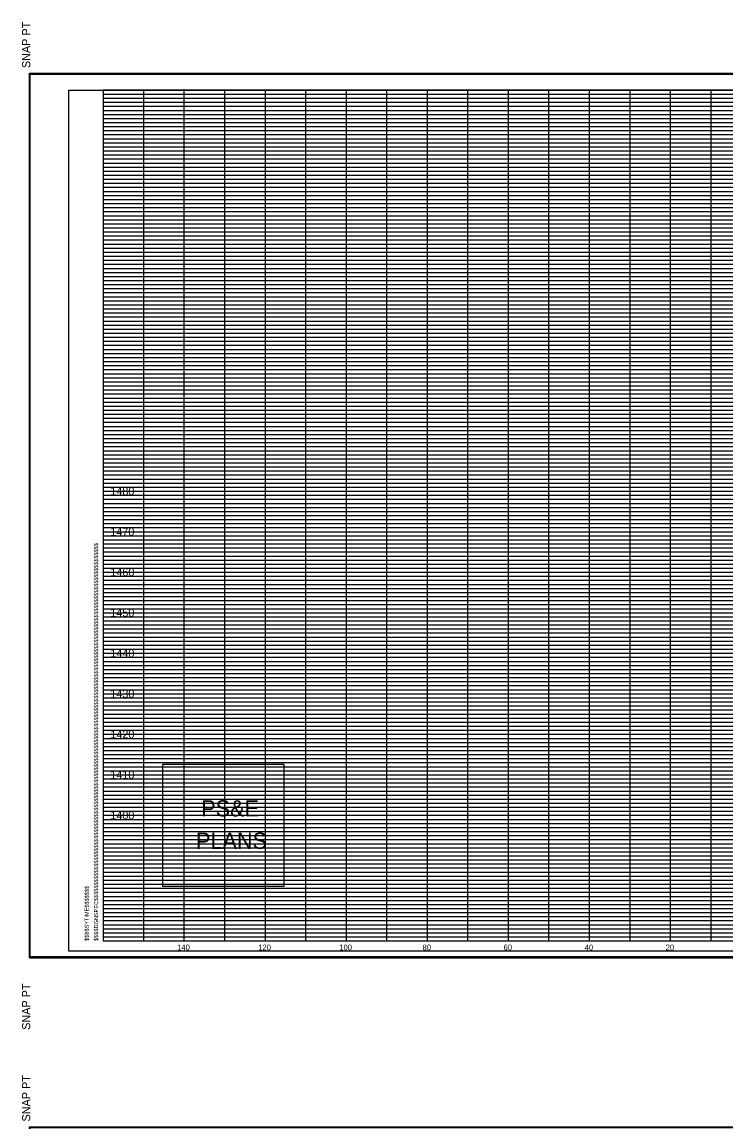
# Model space of a CAD drawing. Extents: x 980 to 2064, y 978 to 2267.
# Drawn here: x 1349.9 to 1523.4, y 1995.5 to 2266.8 of the extents above; entities that cross this region are included whole.
import ezdxf

# ---------------------------------------------------------------- set-up
doc = ezdxf.new("R2010")
doc.units = 0
for name, color, linetype in [('Default', 7, 'Continuous'), ('DESIGN - SHEET - Corner Text', 7, 'Continuous'), ('DESIGN - SHEET - Light Grid', 7, 'Continuous'), ('DESIGN - SHEET - Linework', 7, 'Continuous'), ('DESIGN - SHEET - Plot Shape', 7, 'Continuous')]:
    doc.layers.add(name, color=color, linetype=linetype)

# ---------------------------------------------------------------- blocks, each defined once
blk = doc.blocks.new('XSTSHT')
at = {"layer": 'DESIGN - SHEET - Light Grid'}
for p, q in [((0, 20.9), (8, 20.9)), ((8, 20.9), (16, 20.9)), ((0, 20.8), (8, 20.8)), ((0, 20.7), (8, 20.7)), ((8, 20.8), (16, 20.8)), ((8, 20.7), (16, 20.7)), ((0, 20.6), (8, 20.6)), ((0, 20.5), (8, 20.5)), ((0, 20.4), (8, 20.4)), ((8, 20.6), (16, 20.6)), ((8, 20.5), (16, 20.5)), ((8, 20.4), (16, 20.4)), ((0, 20.3), (8, 20.3)), ((0, 20.2), (8, 20.2)), ((0, 20.1), (8, 20.1)), ((8, 20.3), (16, 20.3)), ((8, 20.2), (16, 20.2)), ((8, 20.1), (16, 20.1)), ((0, 19.9), (8, 19.9)), ((8, 19.9), (16, 19.9)), ((0, 19.8), (8, 19.8)), ((0, 19.7), (8, 19.7)), ((0, 19.6), (8, 19.6)), ((8, 19.8), (16, 19.8)), ((8, 19.7), (16, 19.7)), ((8, 19.6), (16, 19.6)), ((0, 19.5), (8, 19.5)), ((0, 19.4), (8, 19.4)), ((0, 19.3), (8, 19.3)), ((8, 19.5), (16, 19.5)), ((8, 19.4), (16, 19.4)), ((8, 19.3), (16, 19.3)), ((0, 19.2), (8, 19.2)), ((0, 19.1), (8, 19.1)), ((8, 19.2), (16, 19.2)), ((8, 19.1), (16, 19.1)), ((0, 18.9), (8, 18.9)), ((0, 18.8), (8, 18.8)), ((8, 18.9), (16, 18.9)), ((8, 18.8), (16, 18.8)), ((0, 18.7), (8, 18.7)), ((0, 18.6), (8, 18.6)), ((0, 18.5), (8, 18.5)), ((8, 18.7), (16, 18.7)), ((8, 18.6), (16, 18.6)), ((8, 18.5), (16, 18.5)), ((0, 18.4), (8, 18.4)), ((0, 18.3), (8, 18.3)), ((0, 18.2), (8, 18.2)), ((8, 18.4), (16, 18.4)), ((8, 18.3), (16, 18.3)), ((8, 18.2), (16, 18.2)), ((0, 18.1), (8, 18.1)), ((8, 18.1), (16, 18.1)), ((0, 17.9), (8, 17.9)), ((0, 17.8), (8, 17.8)), ((0, 17.7), (8, 17.7)), ((8, 17.9), (16, 17.9)), ((8, 17.8), (16, 17.8)), ((8, 17.7), (16, 17.7)), ((0, 17.6), (8, 17.6)), ((0, 17.5), (8, 17.5)), ((0, 17.4), (8, 17.4)), ((8, 17.6), (16, 17.6)), ((8, 17.5), (16, 17.5)), ((8, 17.4), (16, 17.4)), ((0, 17.3), (8, 17.3)), ((0, 17.2), (8, 17.2)), ((0, 17.1), (8, 17.1)), ((8, 17.3), (16, 17.3)), ((8, 17.2), (16, 17.2)), ((8, 17.1), (16, 17.1)), ((0, 16.9), (8, 16.9)), ((8, 16.9), (16, 16.9)), ((0, 16.8), (8, 16.8)), ((0, 16.7), (8, 16.7)), ((0, 16.6), (8, 16.6)), ((8, 16.8), (16, 16.8)), ((8, 16.7), (16, 16.7)), ((8, 16.6), (16, 16.6)), ((0, 16.5), (8, 16.5)), ((0, 16.4), (8, 16.4)), ((0, 16.3), (8, 16.3)), ((8, 16.5), (16, 16.5)), ((8, 16.4), (16, 16.4)), ((8, 16.3), (16, 16.3)), ((0, 16.2), (8, 16.2)), ((0, 16.1), (8, 16.1)), ((8, 16.2), (16, 16.2)), ((8, 16.1), (16, 16.1)), ((0, 15.9), (8, 15.9)), ((0, 15.8), (8, 15.8)), ((8, 15.9), (16, 15.9)), ((8, 15.8), (16, 15.8)), ((0, 15.7), (8, 15.7)), ((0, 15.6), (8, 15.6)), ((0, 15.5), (8, 15.5)), ((8, 15.7), (16, 15.7)), ((8, 15.6), (16, 15.6)), ((8, 15.5), (16, 15.5)), ((0, 15.4), (8, 15.4)), ((0, 15.3), (8, 15.3)), ((0, 15.2), (8, 15.2)), ((8, 15.4), (16, 15.4)), ((8, 15.3), (16, 15.3)), ((8, 15.2), (16, 15.2)), ((0, 15.1), (8, 15.1)), ((8, 15.1), (16, 15.1)), ((0, 14.9), (8, 14.9)), ((0, 14.8), (8, 14.8)), ((0, 14.7), (8, 14.7)), ((8, 14.9), (16, 14.9)), ((8, 14.8), (16, 14.8)), ((8, 14.7), (16, 14.7)), ((0, 14.6), (8, 14.6)), ((0, 14.5), (8, 14.5)), ((0, 14.4), (8, 14.4)), ((8, 14.6), (16, 14.6)), ((8, 14.5), (16, 14.5)), ((8, 14.4), (16, 14.4)), ((0, 14.3), (8, 14.3)), ((0, 14.2), (8, 14.2)), ((8, 14.3), (16, 14.3)), ((8, 14.2), (16, 14.2)), ((0, 14.1), (8, 14.1)), ((0, 13.9), (8, 13.9)), ((8, 14.1), (16, 14.1)), ((8, 13.9), (16, 13.9)), ((0, 13.8), (8, 13.8)), ((0, 13.7), (8, 13.7)), ((0, 13.6), (8, 13.6)), ((8, 13.8), (16, 13.8)), ((8, 13.7), (16, 13.7)), ((8, 13.6), (16, 13.6)), ((0, 13.5), (8, 13.5)), ((0, 13.4), (8, 13.4)), ((0, 13.3), (8, 13.3)), ((8, 13.5), (16, 13.5)), ((8, 13.4), (16, 13.4)), ((8, 13.3), (16, 13.3)), ((0, 13.2), (8, 13.2)), ((0, 13.1), (8, 13.1)), ((8, 13.2), (16, 13.2)), ((8, 13.1), (16, 13.1)), ((0, 12.9), (8, 12.9)), ((0, 12.8), (8, 12.8)), ((8, 12.9), (16, 12.9)), ((8, 12.8), (16, 12.8)), ((0, 12.7), (8, 12.7)), ((0, 12.6), (8, 12.6)), ((0, 12.5), (8, 12.5)), ((8, 12.7), (16, 12.7)), ((8, 12.6), (16, 12.6)), ((8, 12.5), (16, 12.5)), ((0, 12.4), (8, 12.4)), ((0, 12.3), (8, 12.3)), ((8, 12.4), (16, 12.4)), ((8, 12.3), (16, 12.3)), ((0, 12.2), (8, 12.2)), ((0, 12.1), (8, 12.1)), ((8, 12.2), (16, 12.2)), ((8, 12.1), (16, 12.1)), ((0, 11.9), (8, 11.9)), ((0, 11.8), (8, 11.8)), ((0, 11.7), (8, 11.7)), ((8, 11.9), (16, 11.9)), ((8, 11.8), (16, 11.8)), ((8, 11.7), (16, 11.7)), ((0, 11.6), (8, 11.6)), ((0, 11.5), (8, 11.5)), ((0, 11.4), (8, 11.4)), ((8, 11.6), (16, 11.6)), ((8, 11.5), (16, 11.5)), ((8, 11.4), (16, 11.4)), ((0, 11.3), (8, 11.3)), ((0, 11.2), (8, 11.2)), ((8, 11.3), (16, 11.3)), ((8, 11.2), (16, 11.2)), ((0, 11.1), (8, 11.1)), ((0, 10.9), (8, 10.9)), ((8, 11.1), (16, 11.1)), ((8, 10.9), (16, 10.9)), ((0, 10.8), (8, 10.8)), ((0, 10.7), (8, 10.7)), ((0, 10.6), (8, 10.6)), ((8, 10.8), (16, 10.8)), ((8, 10.7), (16, 10.7)), ((8, 10.6), (16, 10.6)), ((0, 10.5), (8, 10.5)), ((0, 10.4), (8, 10.4)), ((8, 10.5), (16, 10.5)), ((8, 10.4), (16, 10.4)), ((0, 10.3), (8, 10.3)), ((0, 10.2), (8, 10.2)), ((0, 10.1), (8, 10.1)), ((8, 10.3), (16, 10.3)), ((8, 10.2), (16, 10.2)), ((8, 10.1), (16, 10.1)), ((0, 9.9), (8, 9.9)), ((0, 9.8), (8, 9.8)), ((8, 9.9), (16, 9.9)), ((8, 9.8), (16, 9.8)), ((0, 9.7), (8, 9.7)), ((0, 9.6), (8, 9.6)), ((0, 9.5), (8, 9.5)), ((8, 9.7), (16, 9.7)), ((8, 9.6), (16, 9.6)), ((8, 9.5), (16, 9.5)), ((0, 9.4), (8, 9.4)), ((0, 9.3), (8, 9.3)), ((8, 9.4), (16, 9.4)), ((8, 9.3), (16, 9.3)), ((0, 9.2), (8, 9.2)), ((0, 9.1), (8, 9.1)), ((8, 9.2), (16, 9.2)), ((8, 9.1), (16, 9.1)), ((0, 8.9), (8, 8.9)), ((0, 8.8), (8, 8.8)), ((0, 8.7), (8, 8.7)), ((8, 8.9), (16, 8.9)), ((8, 8.8), (16, 8.8)), ((8, 8.7), (16, 8.7)), ((0, 8.6), (8, 8.6)), ((0, 8.5), (8, 8.5)), ((8, 8.6), (16, 8.6)), ((8, 8.5), (16, 8.5)), ((0, 8.4), (8, 8.4)), ((0, 8.3), (8, 8.3)), ((0, 8.2), (8, 8.2)), ((8, 8.4), (16, 8.4)), ((8, 8.3), (16, 8.3)), ((8, 8.2), (16, 8.2)), ((0, 8.1), (8, 8.1)), ((0, 7.9), (8, 7.9)), ((8, 8.1), (16, 8.1)), ((8, 7.9), (16, 7.9)), ((0, 7.8), (8, 7.8)), ((0, 7.7), (8, 7.7)), ((0, 7.6), (8, 7.6)), ((8, 7.8), (16, 7.8)), ((8, 7.7), (16, 7.7)), ((8, 7.6), (16, 7.6)), ((0, 7.5), (8, 7.5)), ((0, 7.4), (8, 7.4)), ((8, 7.5), (16, 7.5)), ((8, 7.4), (16, 7.4)), ((0, 7.3), (8, 7.3)), ((0, 7.2), (8, 7.2)), ((0, 7.1), (8, 7.1)), ((8, 7.3), (16, 7.3)), ((8, 7.2), (16, 7.2)), ((8, 7.1), (16, 7.1)), ((0, 6.9), (8, 6.9)), ((0, 6.8), (8, 6.8)), ((8, 6.9), (16, 6.9)), ((8, 6.8), (16, 6.8)), ((0, 6.7), (8, 6.7)), ((0, 6.6), (8, 6.6)), ((8, 6.7), (16, 6.7)), ((8, 6.6), (16, 6.6)), ((0, 6.5), (8, 6.5)), ((0, 6.4), (8, 6.4)), ((0, 6.3), (8, 6.3)), ((8, 6.5), (16, 6.5)), ((8, 6.4), (16, 6.4)), ((8, 6.3), (16, 6.3)), ((0, 6.2), (8, 6.2)), ((0, 6.1), (8, 6.1)), ((8, 6.2), (16, 6.2)), ((8, 6.1), (16, 6.1)), ((0, 5.9), (8, 5.9)), ((0, 5.8), (8, 5.8)), ((0, 5.7), (8, 5.7)), ((8, 5.9), (16, 5.9)), ((8, 5.8), (16, 5.8)), ((8, 5.7), (16, 5.7)), ((0, 5.6), (8, 5.6)), ((0, 5.5), (8, 5.5)), ((8, 5.6), (16, 5.6)), ((8, 5.5), (16, 5.5)), ((0, 5.4), (8, 5.4)), ((0, 5.3), (8, 5.3)), ((0, 5.2), (8, 5.2)), ((8, 5.4), (16, 5.4)), ((8, 5.3), (16, 5.3)), ((8, 5.2), (16, 5.2)), ((0, 5.1), (8, 5.1)), ((0, 4.9), (8, 4.9)), ((8, 5.1), (16, 5.1)), ((8, 4.9), (16, 4.9)), ((0, 4.8), (8, 4.8)), ((0, 4.7), (8, 4.7)), ((8, 4.8), (16, 4.8)), ((8, 4.7), (16, 4.7)), ((0, 4.6), (8, 4.6)), ((0, 4.5), (8, 4.5)), ((0, 4.4), (8, 4.4)), ((8, 4.6), (16, 4.6)), ((8, 4.5), (16, 4.5)), ((8, 4.4), (16, 4.4)), ((0, 4.3), (8, 4.3)), ((0, 4.2), (8, 4.2)), ((0, 4.1), (8, 4.1)), ((8, 4.3), (16, 4.3)), ((8, 4.2), (16, 4.2)), ((8, 4.1), (16, 4.1)), ((0, 3.9), (8, 3.9)), ((0, 3.8), (8, 3.8)), ((8, 3.9), (16, 3.9)), ((8, 3.8), (16, 3.8)), ((0, 3.7), (8, 3.7)), ((0, 3.6), (8, 3.6)), ((8, 3.7), (16, 3.7)), ((8, 3.6), (16, 3.6)), ((0, 3.5), (8, 3.5)), ((0, 3.4), (8, 3.4)), ((0, 3.3), (8, 3.3)), ((8, 3.5), (16, 3.5)), ((8, 3.4), (16, 3.4)), ((8, 3.3), (16, 3.3)), ((0, 3.2), (8, 3.2)), ((0, 3.1), (8, 3.1)), ((8, 3.2), (16, 3.2)), ((8, 3.1), (16, 3.1)), ((0, 2.9), (8, 2.9)), ((0, 2.8), (8, 2.8)), ((8, 2.9), (16, 2.9)), ((8, 2.8), (16, 2.8)), ((0, 2.7), (8, 2.7)), ((0, 2.6), (8, 2.6)), ((0, 2.5), (8, 2.5)), ((8, 2.7), (16, 2.7)), ((8, 2.6), (16, 2.6)), ((8, 2.5), (16, 2.5)), ((0, 2.4), (8, 2.4)), ((0, 2.3), (8, 2.3)), ((0, 2.2), (8, 2.2)), ((8, 2.4), (16, 2.4)), ((8, 2.3), (16, 2.3)), ((8, 2.2), (16, 2.2)), ((0, 2.1), (8, 2.1)), ((0, 1.9), (8, 1.9)), ((8, 2.1), (16, 2.1)), ((8, 1.9), (16, 1.9)), ((0, 1.8), (8, 1.8)), ((0, 1.7), (8, 1.7)), ((8, 1.8), (16, 1.8)), ((8, 1.7), (16, 1.7)), ((0, 1.6), (8, 1.6)), ((0, 1.5), (8, 1.5)), ((0, 1.4), (8, 1.4)), ((8, 1.6), (16, 1.6)), ((8, 1.5), (16, 1.5)), ((8, 1.4), (16, 1.4)), ((0, 1.3), (8, 1.3)), ((0, 1.2), (8, 1.2)), ((0, 1.1), (8, 1.1)), ((8, 1.3), (16, 1.3)), ((8, 1.2), (16, 1.2)), ((8, 1.1), (16, 1.1)), ((0, 0.9), (8, 0.9)), ((8, 0.9), (16, 0.9)), ((0, 0.8), (8, 0.8)), ((0, 0.7), (8, 0.7)), ((0, 0.6), (8, 0.6)), ((8, 0.8), (16, 0.8)), ((8, 0.7), (16, 0.7)), ((8, 0.6), (16, 0.6)), ((0, 0.5), (8, 0.5)), ((0, 0.4), (8, 0.4)), ((0, 0.3), (8, 0.3)), ((8, 0.5), (16, 0.5)), ((8, 0.4), (16, 0.4)), ((8, 0.3), (16, 0.3)), ((0, 0.2), (8, 0.2)), ((0, 0.1), (8, 0.1)), ((8, 0.2), (16, 0.2)), ((8, 0.1), (16, 0.1))]:
    blk.add_line(p, q, dxfattribs=at)
at = {"layer": 'DESIGN - SHEET - Linework'}
for p, q in [((-1.823, -0.414), (-1.823, 21.414)), ((-1.823, 21.414), (32.217, 21.414)), ((1, 0), (1, 21)), ((2, 0), (2, 21)), ((3, 0), (3, 21)), ((4, 0), (4, 21)), ((5, 0), (5, 21)), ((6, 0), (6, 21)), ((7, 0), (7, 21)), ((8, 0), (8, 21)), ((9, 0), (9, 21)), ((10, 0), (10, 21)), ((11, 0), (11, 21)), ((12, 0), (12, 21)), ((13, 0), (13, 21)), ((14, 0), (14, 21)), ((15, 0), (15, 21)), ((0, 20), (28, 20)), ((0, 19), (32, 19)), ((0, 18), (32, 18)), ((0, 17), (32, 17)), ((0, 16), (32, 16)), ((0, 15), (32, 15)), ((0, 14), (32, 14)), ((0, 13), (32, 13)), ((0, 12), (32, 12)), ((0, 11), (32, 11)), ((0, 10), (32, 10)), ((0, 9), (32, 9)), ((0, 8), (32, 8)), ((0, 7), (32, 7)), ((0, 6), (32, 6)), ((0, 5), (32, 5)), ((0, 4), (32, 4)), ((0, 3), (32, 3)), ((0, 2), (32, 2)), ((0, 1), (32, 1)), ((-1.823, -0.414), (32.217, -0.414))]:
    blk.add_line(p, q, dxfattribs=at)
blk.add_lwpolyline([(0, 21), (0, 0), (32, 0), (32, 21), (0, 21)], dxfattribs=at)
at = {"layer": 'DESIGN - SHEET - Plot Shape'}
for points in [[(-1.803, 21.394), (32.197, 21.394), (32.197, -0.394), (-1.803, -0.394)], [(-0.85, 21), (32, 21), (32, -0.25), (-0.85, -0.25)]]:
    blk.add_lwpolyline(points, close=True, dxfattribs=at)
at = {"layer": 'DESIGN - SHEET - Corner Text'}
for s, height, p in [('  SNAP PT', 0.2, (-1.803, 21.394)), ('$$$$DGNSPEC$$$$$$$$$$$$$$$$$$$$$$$$$$$$$$$$$$$$$$$$$$$$$$$$$$$$$$$$$$$$$$$$$$$$$$$$$$$$$$$$$$$$$$$$$$$$$$$$$$$$$$$$$$$$$$$$$$$', 0.100002, (-0.126, 0)), ('$$$$SYTIME$$$$$$$', 0.1, (-0.358, 0)), ('SNAP PT  ', 0.2, (-1.803, -2.194))]:
    blk.add_text(s, height=height, rotation=90, dxfattribs=at).set_placement(p)

msp = doc.modelspace()

# ---------------------------------------------------------------- linework, layer by layer
at = {"layer": 'DESIGN - SHEET - Corner Text'}
msp.add_lwpolyline([(1384.65, 2083.54), (1384.65, 2053.54), (1414.65, 2053.54), (1414.65, 2083.54)], close=True, dxfattribs=at)

# ---------------------------------------------------------------- block references
at = {"layer": 'Default', "xscale": 10, "yscale": 10}
for p in [(1370, 2040), (1370, 1780)]:
    msp.add_blockref('XSTSHT', p, dxfattribs=at)

# ---------------------------------------------------------------- texts
at = {"layer": 'Default'}
for s, height, p in [('     1480     ', 2, (1368.01, 2150)), ('     1470     ', 2, (1368.01, 2140)), ('     1460     ', 2, (1368.01, 2130)), ('     1450     ', 2, (1368.01, 2120)), ('     1440     ', 2, (1368.01, 2110)), ('     1430     ', 2, (1368.01, 2100)), ('     1420     ', 2, (1368.01, 2090)), ('     1410     ', 2, (1368.01, 2080)), ('     1400     ', 2, (1368.01, 2070)), ('     140     ', 1.4, (1385.65, 2037.7)), ('     120     ', 1.4, (1405.65, 2037.7)), ('     100     ', 1.4, (1425.65, 2037.7)), ('     80     ', 1.4, (1446.2, 2037.7)), ('     60     ', 1.4, (1466.2, 2037.7)), ('     40     ', 1.4, (1486.2, 2037.7)), ('     20     ', 1.4, (1506.2, 2037.7))]:
    msp.add_text(s, height=height, dxfattribs=at).set_placement(p)
at = {"layer": 'DESIGN - SHEET - Corner Text'}
for s, p in [('PS&E', (1394.17, 2070.72)), ('PLANS', (1392.88, 2062.72))]:
    msp.add_text(s, height=4, dxfattribs=at).set_placement(p)

doc.saveas('drawing.dxf')
